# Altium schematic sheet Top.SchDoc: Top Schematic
size A4; Date: Not used; ApprovedBy: Not used; CheckedBy: Not used; Author: Not used; CompanyName: STMicroelectronics; DrawnBy: Not used; Engineer: Not used; Organization: Not used; Address1: Not used; Address2: Not used; Address3: Not used; Address4: Not used; DocumentNumber: Not used; Revision: Not used; SheetNumber: 2; SheetTotal: 6
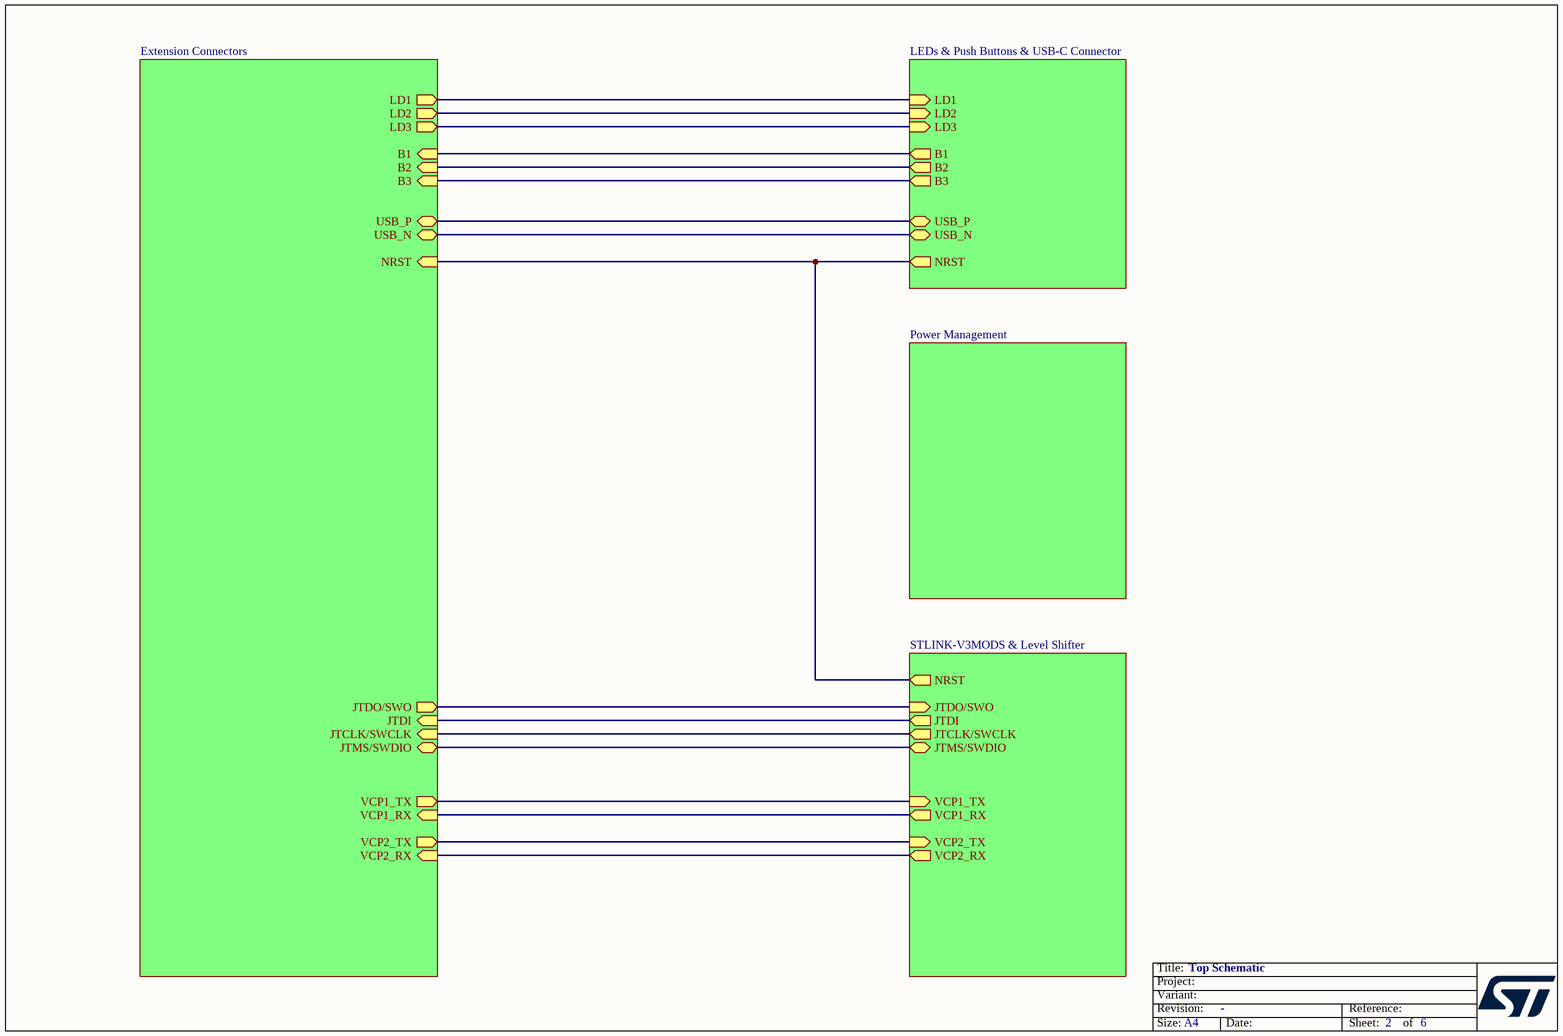
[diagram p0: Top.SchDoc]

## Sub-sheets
Extension Connectors = Extension_CN.SchDoc: VCP1_TX (out), VCP1_RX (in), VCP2_TX (out), VCP2_RX (in), JTDO/SWO (out), JTDI (in), JTCLK/SWCLK (in), JTMS/SWDIO (bidir), LD1 (out), LD2 (out), LD3 (out), B1 (in), B2 (in), B3 (in), USB_P (bidir), USB_N (bidir), NRST (in)
LEDs & Push Buttons & USB-C Connector = Accessories.SchDoc: LD1 (in), LD2 (in), LD3 (in), B1 (out), B2 (out), B3 (out), USB_P (bidir), USB_N (bidir), NRST (out)
Power Management = Power_Management.SchDoc: no entries
STLINK-V3MODS & Level Shifter = STlink.SchDoc: VCP1_TX (in), VCP1_RX (out), VCP2_TX (in), VCP2_RX (out), JTDO/SWO (in), JTDI (out), JTCLK/SWCLK (out), JTMS/SWDIO (bidir), NRST (out)

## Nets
(unnamed): sheet Extension Connectors/VCP1_TX, sheet STLINK-V3MODS & Level Shifter/VCP1_TX
(unnamed): sheet Extension Connectors/VCP1_RX, sheet STLINK-V3MODS & Level Shifter/VCP1_RX  [a separate net that carries the same name]
(unnamed): sheet Extension Connectors/VCP2_TX, sheet STLINK-V3MODS & Level Shifter/VCP2_TX  [a separate net that carries the same name]
(unnamed): sheet Extension Connectors/VCP2_RX, sheet STLINK-V3MODS & Level Shifter/VCP2_RX  [a separate net that carries the same name]
(unnamed): sheet Extension Connectors/JTDO/SWO, sheet STLINK-V3MODS & Level Shifter/JTDO/SWO  [a separate net that carries the same name]
(unnamed): sheet Extension Connectors/JTDI, sheet STLINK-V3MODS & Level Shifter/JTDI  [a separate net that carries the same name]
(unnamed): sheet Extension Connectors/JTCLK/SWCLK, sheet STLINK-V3MODS & Level Shifter/JTCLK/SWCLK  [a separate net that carries the same name]
(unnamed): sheet Extension Connectors/JTMS/SWDIO, sheet STLINK-V3MODS & Level Shifter/JTMS/SWDIO  [a separate net that carries the same name]
(unnamed): sheet Extension Connectors/LD1, sheet LEDs & Push Buttons & USB-C Connector/LD1  [a separate net that carries the same name]
(unnamed): sheet Extension Connectors/LD2, sheet LEDs & Push Buttons & USB-C Connector/LD2  [a separate net that carries the same name]
(unnamed): sheet Extension Connectors/LD3, sheet LEDs & Push Buttons & USB-C Connector/LD3  [a separate net that carries the same name]
(unnamed): sheet Extension Connectors/B1, sheet LEDs & Push Buttons & USB-C Connector/B1  [a separate net that carries the same name]
(unnamed): sheet Extension Connectors/B2, sheet LEDs & Push Buttons & USB-C Connector/B2  [a separate net that carries the same name]
(unnamed): sheet Extension Connectors/B3, sheet LEDs & Push Buttons & USB-C Connector/B3  [a separate net that carries the same name]
(unnamed): sheet Extension Connectors/USB_P, sheet LEDs & Push Buttons & USB-C Connector/USB_P  [a separate net that carries the same name]
(unnamed): sheet Extension Connectors/USB_N, sheet LEDs & Push Buttons & USB-C Connector/USB_N  [a separate net that carries the same name]
(unnamed): sheet Extension Connectors/NRST, sheet LEDs & Push Buttons & USB-C Connector/NRST, sheet STLINK-V3MODS & Level Shifter/NRST  [a separate net that carries the same name]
